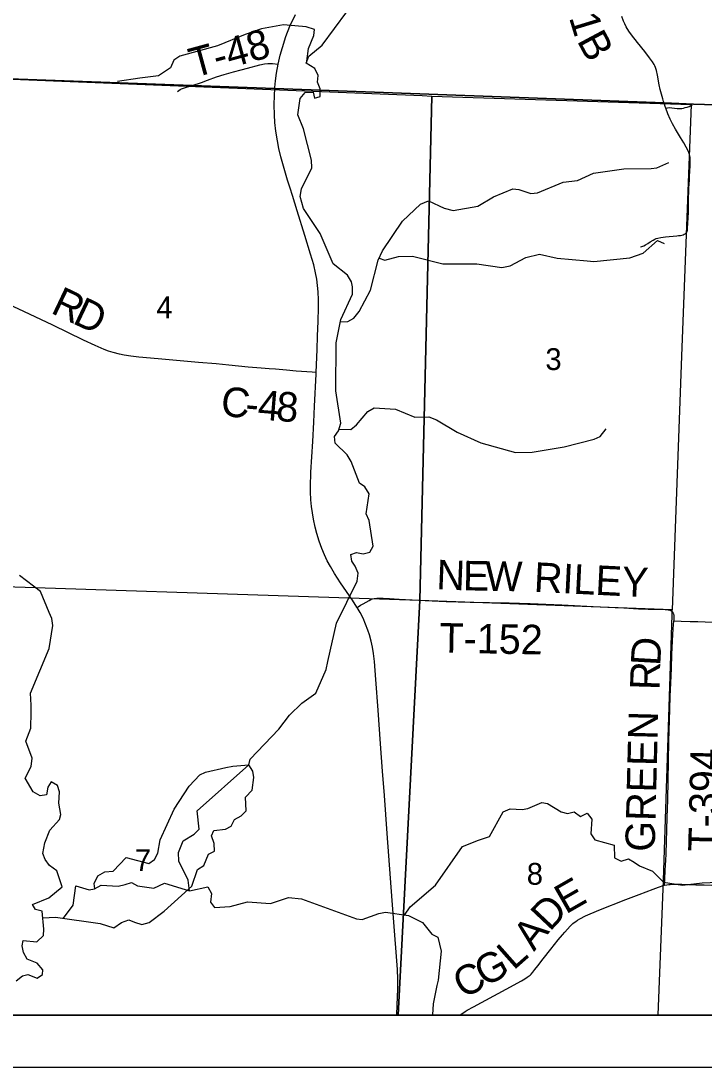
# Model space of a CAD drawing. Extents: x 0 to 34, y 0 to 22.
# Drawn here: x 7.248 to 8.561, y 14.3 to 16.31 of the extents above; entities that cross this region are included whole.
import ezdxf

# ---------------------------------------------------------------- set-up
doc = ezdxf.new("R2010")
doc.units = 0
for name, color, linetype in [('GM_X_County', 7, 'Continuous'), ('GM_X_County_Road', 7, 'Continuous'), ('GM_X_County_Road_Text', 7, 'Continuous'), ('GM_X_Minor_River', 7, 'Continuous'), ('GM_X_Section', 7, 'Continuous'), ('GM_X_Section_Text', 7, 'Continuous'), ('GM_X_State_Route', 7, 'Continuous'), ('GM_X_Township', 7, 'Continuous'), ('GM_X_Township_Road', 7, 'Continuous'), ('GM_X_Township_Road_Text', 7, 'Continuous'), ('GM_X_Township_Subdivision', 7, 'Continuous'), ('SH_Data', 7, 'Continuous')]:
    doc.layers.add(name, color=color, linetype=linetype)

msp = doc.modelspace()

# ---------------------------------------------------------------- linework, layer by layer
at = {"layer": 'GM_X_County'}
msp.add_lwpolyline([(7.0736, 21.2003), (2.6013, 21.2003), (2.6013, 14.4003), (9.4013, 14.4003), (9.4013, 21.1598)], dxfattribs=at)
at = {"layer": 'GM_X_County_Road'}
for points in [[(7.8151, 15.6345), (7.8079, 15.635), (7.777, 15.6372), (7.7585, 15.6389), (7.7369, 15.6408), (7.7248, 15.6418), (7.7096, 15.6428), (7.6848, 15.645), (7.6477, 15.6488), (7.623, 15.651), (7.5889, 15.654), (7.561, 15.6565), (7.5115, 15.6608), (7.4743, 15.664), (7.4589, 15.6657), (7.4465, 15.6676), (7.4374, 15.6695), (7.4253, 15.6727), (7.4164, 15.6756), (7.4076, 15.6789), (7.3904, 15.6863), (7.3679, 15.6968), (7.3091, 15.7252), (7.2641, 15.7465), (7.2134, 15.7702)], [(8.0924, 14.4003), (8.0973, 14.4035), (8.1019, 14.4064), (8.1059, 14.4088), (8.1178, 14.4156), (8.1805, 14.4497), (8.2103, 14.4656), (8.2164, 14.4692), (8.221, 14.4722), (8.2247, 14.4749), (8.2266, 14.4765), (8.2284, 14.4784), (8.2317, 14.4819), (8.2358, 14.487), (8.2415, 14.4943), (8.2514, 14.5075), (8.2663, 14.5264), (8.2803, 14.5439), (8.2888, 14.5539), (8.2933, 14.5592), (8.2983, 14.5648), (8.3036, 14.5702), (8.309, 14.5753), (8.3115, 14.5775), (8.3144, 14.5795), (8.318, 14.582), (8.3221, 14.5845), (8.3331, 14.5902), (8.3587, 14.6013), (8.4108, 14.6215), (8.4364, 14.6311), (8.463, 14.6413), (8.4737, 14.6455), (8.4773, 14.6468), (8.4803, 14.6478), (8.4852, 14.6492)], [(8.4852, 14.6492), (8.4893, 14.65), (8.4932, 14.6505), (8.4957, 14.6508), (8.4983, 14.651), (8.5014, 14.6512), (8.5052, 14.6512), (8.5107, 14.6512), (8.5184, 14.6511), (8.5449, 14.65), (8.5614, 14.6496), (8.5908, 14.6489), (8.6536, 14.6478), (8.7115, 14.6461), (8.7434, 14.645), (8.7936, 14.6437)]]:
    msp.add_lwpolyline(points, dxfattribs=at)
at = {"layer": 'GM_X_Minor_River'}
for points in [[(7.29, 14.5865), (7.3142, 14.5878), (7.4003, 14.5753), (7.4265, 14.5671), (7.4409, 14.5774), (7.4549, 14.5824), (7.4663, 14.5782), (7.4803, 14.5734), (7.4943, 14.5776), (7.5234, 14.5994), (7.5766, 14.6474), (7.5871, 14.6793), (7.5992, 14.687), (7.6085, 14.7086), (7.6199, 14.7148), (7.6194, 14.7292), (7.614, 14.744), (7.6185, 14.7546), (7.6413, 14.7566), (7.6522, 14.7627), (7.6582, 14.7756), (7.6711, 14.7825), (7.6809, 14.7924), (7.6796, 14.8182), (7.6925, 14.832), (7.6954, 14.8562), (7.6938, 14.8684), (7.6858, 14.8805), (7.6884, 14.8915), (7.7434, 14.949), (7.7638, 14.9757), (7.7875, 14.999), (7.8144, 15.018), (7.8346, 15.0637), (7.8379, 15.0789), (7.8543, 15.1525), (7.8941, 15.2335), (7.8963, 15.2491), (7.8901, 15.2624), (7.884, 15.2722), (7.8817, 15.2847), (7.893, 15.2886), (7.9059, 15.2863), (7.9188, 15.2891), (7.9248, 15.3008), (7.917, 15.3501), (7.9113, 15.363), (7.9175, 15.4014), (7.9087, 15.4146), (7.8989, 15.4218), (7.8827, 15.4638), (7.8751, 15.4763), (7.8519, 15.499), (7.8507, 15.5115), (7.8582, 15.5225), (7.8627, 15.5373), (7.8533, 15.5995), (7.8536, 15.6913), (7.8629, 15.7361), (7.8854, 15.7852), (7.8849, 15.7992), (7.8834, 15.8087), (7.8754, 15.8219), (7.8483, 15.8434), (7.8231, 15.9018), (7.791, 15.9498), (7.7844, 15.9725), (7.7874, 15.9873), (7.8069, 16.0276), (7.8065, 16.0428), (7.791, 16.1031), (7.7799, 16.1296), (7.7847, 16.1611), (7.7941, 16.1729), (7.8093, 16.1733), (7.8124, 16.1616), (7.823, 16.1647), (7.8233, 16.1795), (7.8179, 16.1927), (7.8194, 16.2056), (7.8129, 16.2185), (7.7958, 16.2291), (7.8014, 16.2427), (7.8271, 16.2637), (7.8741, 16.3277)], [(7.7974, 16.233), (7.8006, 16.2571), (7.811, 16.2822), (7.8121, 16.2936), (7.7958, 16.2989), (7.7526, 16.3028), (7.7102, 16.2951), (7.6791, 16.2839), (7.6258, 16.2624), (7.5531, 16.2424), (7.5414, 16.2347), (7.5354, 16.2199), (7.512, 16.2046), (7.4764, 16.2003), (7.4332, 16.1936)], [(7.862, 15.7318), (7.8762, 15.7324), (7.8875, 15.7389), (7.8981, 15.7515), (7.9198, 15.7929), (7.9347, 15.8503), (7.9426, 15.8685), (7.9814, 15.9252), (8.0157, 15.958), (8.0312, 15.9645), (8.0612, 15.9506), (8.0787, 15.9458), (8.1264, 15.9544), (8.1563, 15.9723), (8.1933, 15.9873), (8.2047, 15.9862), (8.2282, 15.9783), (8.2407, 15.9799), (8.2899, 16.0002), (8.3176, 16.0034), (8.3486, 16.0176), (8.4069, 16.0262), (8.4596, 16.0264), (8.4702, 16.028), (8.4936, 16.038)], [(7.9365, 15.8544), (7.9476, 15.8507), (7.9734, 15.8573), (8.0003, 15.8582), (8.0587, 15.8433), (8.1239, 15.8436), (8.172, 15.8366), (8.1883, 15.8393), (8.2186, 15.8554), (8.2447, 15.8619), (8.2788, 15.8545), (8.3361, 15.8491), (8.349, 15.8476), (8.4183, 15.8548), (8.444, 15.864), (8.4716, 15.888), (8.4841, 15.8827)], [(7.8591, 15.5256), (7.8821, 15.5253), (7.893, 15.534), (7.9145, 15.5596), (7.927, 15.5664), (7.9679, 15.564), (8.0048, 15.549), (8.032, 15.5495), (8.0468, 15.5435), (8.0864, 15.5201), (8.1316, 15.4991), (8.1987, 15.4808), (8.2306, 15.4813), (8.2923, 15.4918), (8.3495, 15.5061), (8.3612, 15.5115), (8.3729, 15.526)], [(7.2383, 14.4653), (7.2507, 14.4752), (7.2613, 14.4775), (7.2792, 14.4704), (7.2894, 14.4773), (7.2901, 14.4868), (7.279, 14.4996), (7.26, 14.5071), (7.2528, 14.52), (7.2501, 14.5329), (7.2523, 14.5431), (7.2781, 14.5402), (7.2913, 14.5524), (7.292, 14.5646), (7.2888, 14.5995), (7.2759, 14.6024), (7.2701, 14.6123), (7.3015, 14.6249), (7.3268, 14.6463), (7.3168, 14.6766), (7.3028, 14.6872), (7.2944, 14.6989), (7.2898, 14.7099), (7.2935, 14.7308), (7.3032, 14.7551), (7.322, 14.7757), (7.3243, 14.7852), (7.3204, 14.8068), (7.3222, 14.8284), (7.3179, 14.8405), (7.3058, 14.8481), (7.2994, 14.8378), (7.2968, 14.823), (7.2847, 14.8207), (7.2714, 14.8286), (7.2561, 14.8547), (7.2677, 14.8771), (7.2696, 14.8931), (7.2569, 14.926), (7.267, 14.9511), (7.2672, 14.9818), (7.2672, 14.9951), (7.2659, 15.0183), (7.3019, 15.1042), (7.3089, 15.1482), (7.3073, 15.1619), (7.3023, 15.1732), (7.2851, 15.2138), (7.2451, 15.2443)], [(7.3896, 14.6423), (7.3886, 14.6523), (7.3953, 14.6671), (7.4093, 14.6751), (7.4249, 14.6763), (7.4501, 14.7022), (7.4938, 14.6907), (7.5043, 14.6983), (7.5111, 14.7109), (7.5155, 14.7363), (7.5425, 14.7956), (7.5711, 14.8394), (7.5915, 14.8611), (7.6028, 14.8665), (7.6418, 14.8754), (7.6551, 14.8777), (7.6858, 14.8805)], [(7.5718, 14.6387), (7.569, 14.6588), (7.5514, 14.6951), (7.5505, 14.7118), (7.5595, 14.7342), (7.5807, 14.7472), (7.5901, 14.7571), (7.5865, 14.7924), (7.6858, 14.8805)], [(7.9853, 14.5919), (7.996, 14.6075), (8.0447, 14.6491), (8.0966, 14.7233), (8.1273, 14.7356), (8.1488, 14.7429), (8.1751, 14.7901), (8.188, 14.7962), (8.2115, 14.7944), (8.2225, 14.7964), (8.2493, 14.8083), (8.26, 14.806), (8.2866, 14.7902), (8.2987, 14.7868), (8.3112, 14.7903), (8.3234, 14.7813), (8.3362, 14.7878), (8.345, 14.776), (8.3433, 14.748), (8.3509, 14.7366), (8.3885, 14.7262), (8.389, 14.7015), (8.4019, 14.6955), (8.4155, 14.6997), (8.4269, 14.6937), (8.4368, 14.6865), (8.4622, 14.676), (8.4828, 14.6549), (8.5196, 14.6493), (8.5575, 14.654), (8.6185, 14.6566)], [(7.3296, 14.5856), (7.3479, 14.6107), (7.353, 14.6479), (7.3788, 14.6401), (7.389, 14.642), (7.4019, 14.6493), (7.4345, 14.6475), (7.4481, 14.6506), (7.4602, 14.6541), (7.472, 14.6477), (7.5035, 14.6433), (7.5235, 14.6532), (7.5717, 14.6387), (7.6069, 14.646), (7.6142, 14.6332), (7.612, 14.6164), (7.6196, 14.6066), (7.6499, 14.6083), (7.6836, 14.6175), (7.7276, 14.6143), (7.7624, 14.6255), (7.7871, 14.6229), (7.8926, 14.5847), (7.9036, 14.5832), (7.9358, 14.5951), (7.9487, 14.5971), (7.993, 14.5908), (8.02, 14.5773), (8.0379, 14.5554), (8.0493, 14.5493), (8.0559, 14.5224), (8.0497, 14.467), (8.0475, 14.4567), (8.0405, 14.421), (8.0389, 14.4003)]]:
    msp.add_lwpolyline(points, dxfattribs=at)
at = {"layer": 'GM_X_Section'}
for p, q in [((6.9645, 14.4003), (7.9727, 14.4003)), ((7.9727, 14.4003), (8.4728, 14.4003))]:
    msp.add_line(p, q, dxfattribs=at)
for points in [[(7.0538, 16.2053), (7.5347, 16.1861), (8.0188, 16.1667), (8.0374, 16.1659), (8.0145, 15.1965), (7.0022, 15.2299), (7.0338, 16.2061)], [(8.5365, 16.1498), (8.5177, 15.6658), (8.4996, 15.1781), (8.0145, 15.1965), (8.0374, 16.1659)]]:
    msp.add_lwpolyline(points, close=True, dxfattribs=at)
for points in [[(7.9727, 14.4003), (8.0145, 15.1965), (7.0022, 15.2299), (6.9645, 14.4003)], [(8.4728, 14.4003), (8.4829, 14.6582), (8.4998, 15.1685), (8.4996, 15.1781), (8.0145, 15.1965), (7.9727, 14.4003)]]:
    msp.add_lwpolyline(points, dxfattribs=at)
at = {"layer": 'GM_X_State_Route'}
for points in [[(7.7653, 15.9887), (7.7603, 16.0044), (7.7523, 16.0312), (7.7475, 16.0493), (7.7437, 16.0651), (7.7407, 16.0796), (7.7377, 16.0986), (7.736, 16.1147), (7.7351, 16.13), (7.7347, 16.1488), (7.7349, 16.1671), (7.7357, 16.1804), (7.7357, 16.1813), (7.7358, 16.1823), (7.737, 16.195), (7.7389, 16.2099), (7.7422, 16.2274), (7.7463, 16.2446), (7.7503, 16.2594), (7.7569, 16.28), (7.7648, 16.3002), (7.7753, 16.3227)], [(7.8051, 15.4366), (7.8053, 15.443), (7.8086, 15.5021), (7.8106, 15.5389), (7.8124, 15.5699), (7.815, 15.6312), (7.8151, 15.6345), (7.817, 15.6789), (7.8179, 15.7043), (7.8191, 15.7333), (7.8199, 15.7587), (7.8201, 15.774), (7.8193, 15.7895), (7.8182, 15.8018), (7.8164, 15.8141), (7.8142, 15.8263), (7.8106, 15.8413), (7.8047, 15.8622), (7.7938, 15.8978), (7.779, 15.9452), (7.7697, 15.9748), (7.7653, 15.9887)], [(7.9703, 14.4003), (7.9711, 14.4184), (7.9721, 14.4501), (7.9721, 14.4687), (7.9714, 14.4873), (7.97, 14.5121), (7.9662, 14.5616), (7.9616, 14.6196), (7.9521, 14.7486), (7.9466, 14.8218), (7.9429, 14.8682), (7.9393, 14.9209), (7.9345, 14.9859), (7.9298, 15.0447), (7.9272, 15.0788), (7.9254, 15.0942), (7.9235, 15.1064), (7.9209, 15.1185), (7.9177, 15.1304), (7.9148, 15.1393), (7.9104, 15.1508), (7.9054, 15.1621), (7.8998, 15.1731), (7.8939, 15.1832), (7.8935, 15.1838), (7.8851, 15.1968), (7.8623, 15.2302), (7.8506, 15.2485), (7.8427, 15.2619), (7.8367, 15.2725), (7.8314, 15.2838), (7.8263, 15.296), (7.8211, 15.3105), (7.8166, 15.3251), (7.8134, 15.3374), (7.8099, 15.3528), (7.808, 15.3646), (7.8061, 15.3773), (7.805, 15.39), (7.8043, 15.4054), (7.8045, 15.4214), (7.8051, 15.4366)]]:
    msp.add_lwpolyline(points, dxfattribs=at)
at = {"layer": 'GM_X_Township'}
for points in [[(6.2234, 21.2003), (6.1733, 19.6859), (6.1731, 19.6818), (6.1731, 19.6616), (6.1717, 19.6397), (6.1473, 18.845), (6.11, 17.7459), (6.0911, 17.2548), (6.0778, 16.7443), (6.0664, 16.4042), (6.0598, 16.2379), (6.2085, 16.2337), (6.3056, 16.228), (6.5048, 16.2253), (7.5772, 16.1862), (7.7357, 16.1804), (8.4842, 16.1527), (8.5405, 16.1503), (9.1818, 16.131), (9.4013, 16.1226)], [(9.1818, 16.131), (8.5405, 16.1503), (8.4842, 16.1527), (7.7357, 16.1804), (7.5772, 16.1862), (6.5048, 16.2253)], [(6.0009, 14.4003), (9.4013, 14.4003), (9.4013, 16.1226)]]:
    msp.add_lwpolyline(points, dxfattribs=at)
at = {"layer": 'GM_X_Township_Road'}
for points in [[(8.4832, 16.1556), (8.4816, 16.1607), (8.479, 16.1694), (8.4767, 16.1784), (8.4748, 16.1875), (8.4715, 16.2058), (8.4694, 16.2149), (8.4677, 16.2207), (8.4661, 16.2237), (8.4649, 16.2264), (8.4617, 16.2317), (8.4564, 16.2393), (8.4469, 16.2516), (8.4333, 16.2685), (8.4217, 16.2832), (8.4163, 16.2908), (8.4115, 16.2988), (8.4086, 16.3043), (8.4062, 16.31), (8.4031, 16.3188)], [(7.5763, 16.1859), (7.5772, 16.1862), (7.5949, 16.1918), (7.6065, 16.1961), (7.6238, 16.2026), (7.6385, 16.2074), (7.6563, 16.2125), (7.6713, 16.2162), (7.6833, 16.2195), (7.7073, 16.2258), (7.7163, 16.2278), (7.7225, 16.2286), (7.7256, 16.2286), (7.7315, 16.2283), (7.7422, 16.2274)], [(7.549, 16.1746), (7.5512, 16.1767), (7.5538, 16.1784), (7.5566, 16.1798), (7.5624, 16.1819), (7.5763, 16.1859)], [(8.4877, 16.1423), (8.4864, 16.1459), (8.4841, 16.1527), (8.4832, 16.1556)], [(8.4387, 15.876), (8.4415, 15.8766), (8.4451, 15.878), (8.4483, 15.8797), (8.4528, 15.8822), (8.4576, 15.8854), (8.4629, 15.8888), (8.4663, 15.8906), (8.4689, 15.8919), (8.472, 15.8928), (8.4778, 15.8942), (8.4871, 15.8954), (8.5088, 15.8971), (8.5122, 15.8975), (8.5155, 15.898), (8.5181, 15.8985), (8.5207, 15.8993), (8.5227, 15.9001), (8.5237, 15.9007), (8.5247, 15.9013), (8.526, 15.9023), (8.5273, 15.9035), (8.528, 15.9045), (8.5284, 15.9052), (8.5286, 15.9059), (8.5289, 15.9072), (8.5293, 15.9091), (8.5295, 15.9112), (8.5309, 15.9423), (8.531, 15.9484), (8.5313, 15.9639), (8.5313, 15.9732), (8.5315, 15.9794), (8.532, 15.9887), (8.5329, 16.004), (8.533, 16.0071), (8.5333, 16.0132), (8.5336, 16.0194), (8.5338, 16.0224), (8.5339, 16.0255), (8.5341, 16.0285), (8.5345, 16.0377), (8.5345, 16.0445), (8.5342, 16.0485), (8.5338, 16.0511), (8.533, 16.0535), (8.5319, 16.0571), (8.5298, 16.0618), (8.5269, 16.0675), (8.5223, 16.0756), (8.5157, 16.0861), (8.5059, 16.1021), (8.5001, 16.1126), (8.4958, 16.1215), (8.4916, 16.1316), (8.4877, 16.1423)], [(7.8939, 15.1832), (7.9008, 15.1872), (7.9054, 15.1899), (7.9173, 15.1965), (7.9204, 15.1981), (7.9239, 15.1994), (7.9265, 15.2), (7.9294, 15.2004), (7.9318, 15.2007), (7.9352, 15.2009), (7.944, 15.2007), (7.9563, 15.2), (7.975, 15.1991), (8.0246, 15.1966), (8.065, 15.1944), (8.1116, 15.1931), (8.1861, 15.1916), (8.2265, 15.1906), (8.2876, 15.1879), (8.3479, 15.185), (8.39, 15.1829), (8.4068, 15.182), (8.4348, 15.1806), (8.4535, 15.1798), (8.486, 15.1791), (8.4906, 15.1789), (8.4922, 15.1786), (8.4937, 15.1783), (8.4951, 15.1779), (8.4958, 15.1776), (8.4965, 15.1773), (8.4971, 15.177), (8.4978, 15.1766), (8.4991, 15.1756), (8.4997, 15.175), (8.5002, 15.1744), (8.5008, 15.1737), (8.5013, 15.1728), (8.5017, 15.1721), (8.5023, 15.1708), (8.5025, 15.1701), (8.5028, 15.1689), (8.503, 15.1678), (8.5031, 15.1666), (8.5032, 15.165), (8.5032, 15.1624), (8.5031, 15.157)], [(8.4852, 14.6492), (8.4857, 14.6619), (8.4863, 14.6767), (8.487, 14.6884), (8.4874, 14.6968), (8.4879, 14.7098), (8.4904, 14.7792), (8.4912, 14.8134), (8.4924, 14.8879), (8.4935, 14.9252), (8.4952, 14.9875), (8.4961, 15.0123), (8.4972, 15.0372), (8.4982, 15.0654), (8.4993, 15.0931), (8.5013, 15.1307), (8.5018, 15.1418), (8.5025, 15.1497), (8.5031, 15.157)], [(8.5031, 15.157), (8.5168, 15.1566), (8.5342, 15.1561), (8.5492, 15.1559), (8.563, 15.1556), (8.5812, 15.1549), (8.6087, 15.1538), (8.6578, 15.1529)]]:
    msp.add_lwpolyline(points, dxfattribs=at)
at = {"layer": 'GM_X_Township_Subdivision'}
msp.add_lwpolyline([(8.4877, 16.1423), (8.491, 16.1431), (8.4944, 16.1435), (8.4991, 16.1434), (8.5091, 16.142), (8.5123, 16.1418), (8.5155, 16.1418), (8.5186, 16.1421), (8.5217, 16.1427), (8.5246, 16.1436), (8.5287, 16.1445), (8.5326, 16.1459), (8.5356, 16.1475), (8.5385, 16.1488)], dxfattribs=at)
at = {"layer": 'SH_Data'}
for p, q in [((2.6, 14.3997), (9.4, 14.3997)), ((2.5, 14.2997), (9.5, 14.2997))]:
    msp.add_line(p, q, dxfattribs=at)

# ---------------------------------------------------------------- texts
at = {"layer": 'GM_X_County_Road_Text'}
for s, rotation, p in [('R', 334.6004, (7.303, 15.7499)), ('D', 334.7526, (7.345, 15.7299)), ('C', 353.8762, (7.6303, 15.5519)), ('4', 355.3454, (7.7015, 15.5446)), ('8', 355.9919, (7.7371, 15.5417)), ('-', 354.6552, (7.6775, 15.5468)), ('E', 29.7598, (8.2951, 14.5926)), ('D', 46.6978, (8.2643, 14.5589)), ('A', 51.6918, (8.2341, 14.5207)), ('G', 28.5529, (8.1394, 14.4526)), ('L', 41.5568, (8.1948, 14.4845)), ('C', 29.0303, (8.0987, 14.43))]:
    msp.add_text(s, height=0.0568, rotation=rotation, dxfattribs=at).set_placement(p)
at = {"layer": 'GM_X_Section_Text'}
for s, p in [('4', (7.5081, 15.7387)), ('3', (8.256, 15.6393)), ('7', (7.4668, 14.6765)), ('8', (8.2202, 14.6501))]:
    msp.add_text(s, height=0.0419, rotation=0, dxfattribs=at).set_placement(p)
at = {"layer": 'GM_X_Township_Road_Text'}
for s, height, rotation, p in [('1', 0.0568, 286.9476, (8.301, 16.317)), ('T-48', 0.05682, 15.2922, (7.5803, 16.2007)), ('B', 0.0568, 298.1113, (8.3158, 16.2724)), ('N', 0.0568, 357.6315, (8.0457, 15.2181)), ('E', 0.0568, 358.9489, (8.0971, 15.216)), ('W', 0.0568, 358.9861, (8.1396, 15.2152)), ('RILEY', 0.05682, 357.1846, (8.233, 15.2132)), ('T-152', 0.05682, 358.8826, (8.0519, 15.0964)), ('D', 0.0568, 86.8254, (8.4767, 15.0699)), ('R', 0.0568, 88.3293, (8.4753, 15.0237)), ('GREEN', 0.05682, 88.5559, (8.4661, 14.713)), ('T-394', 0.05682, 88.5955, (8.5871, 14.7133))]:
    msp.add_text(s, height=height, rotation=rotation, dxfattribs=at).set_placement(p)

doc.saveas('drawing.dxf')
